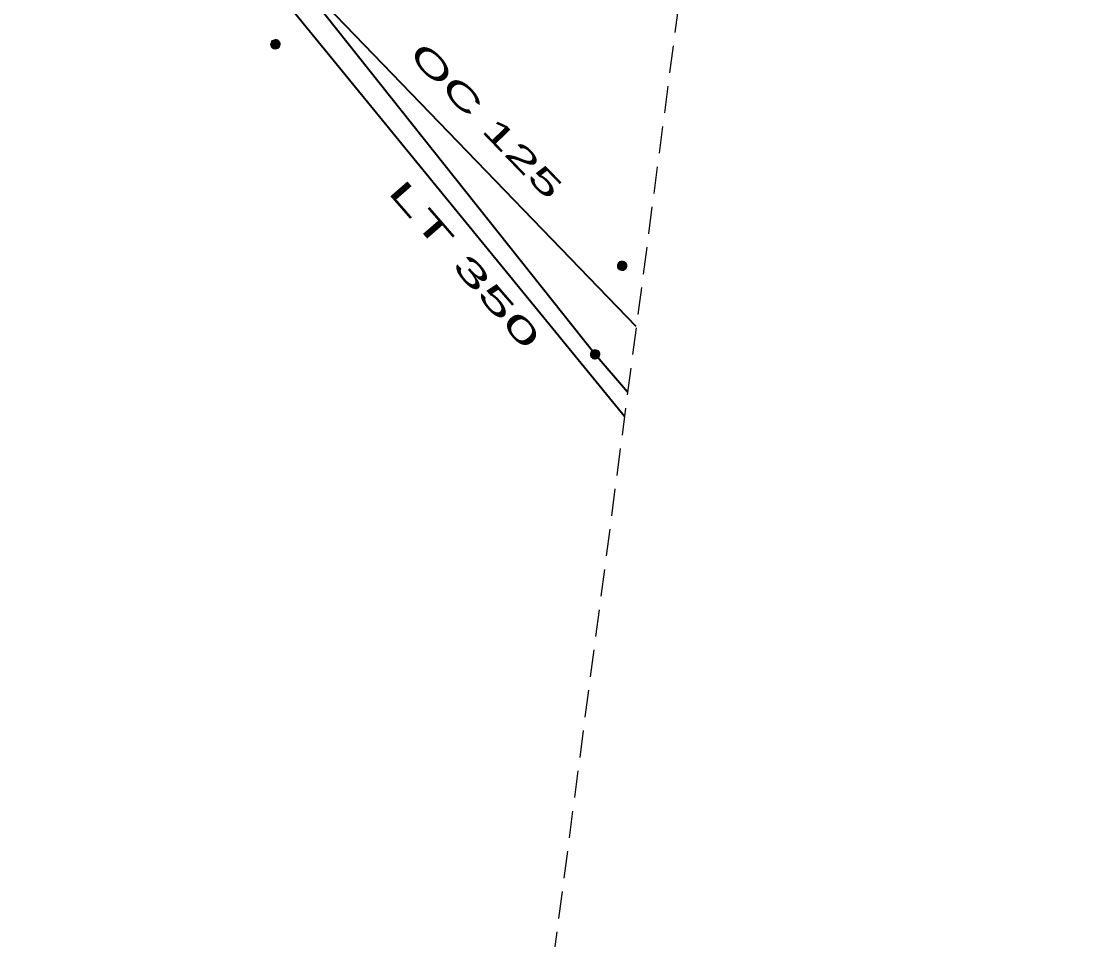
# Model space of a CAD drawing. Extents: x -867121 to -866743, y -1014362 to -1014088.
# Drawn here: x -866794.7 to -866742.8, y -1014314.8 to -1014270 of the extents above; entities that cross this region are included whole.
import ezdxf

# ---------------------------------------------------------------- set-up
doc = ezdxf.new("R2010")
doc.units = 0
doc.header["$LTSCALE"] = 0.44
doc.linetypes.add('MEDIUM_DASHED', pattern=[4.5, 3, -1.5])
for name, color, linetype, lineweight in [('1', 7, 'Continuous', 35), ('21', 7, 'Continuous', 35), ('25', 7, 'Continuous', 13), ('32', 7, 'Continuous', 13), ('62', 7, 'MEDIUM_DASHED', 25)]:
    doc.layers.add(name, color=color, linetype=linetype, lineweight=lineweight)

msp = doc.modelspace()

# ---------------------------------------------------------------- linework, layer by layer
at = {"layer": '1'}
for p, q in [((-866764.699, -1014284.885), (-866792.574, -1014256.008)), ((-866765.275, -1014289.274), (-866791.98, -1014256.58))]:
    msp.add_line(p, q, dxfattribs=at)
at = {"layer": '21'}
msp.add_lwpolyline([(-866765.121, -1014288.097), (-866766.707, -1014286.245), (-866790.339, -1014256.505)], dxfattribs=at)
at = {"layer": '25'}
for points in [[(-866782.059, -1014271.13), (-866782.065, -1014271.078), (-866782.082, -1014271.028), (-866782.111, -1014270.984), (-866782.148, -1014270.947), (-866782.193, -1014270.92), (-866782.243, -1014270.903), (-866782.296, -1014270.899), (-866782.348, -1014270.906), (-866782.397, -1014270.925), (-866782.44, -1014270.954), (-866782.476, -1014270.993), (-866782.502, -1014271.038), (-866782.518, -1014271.089), (-866782.521, -1014271.141), (-866782.513, -1014271.193), (-866782.493, -1014271.242), (-866782.462, -1014271.285), (-866782.423, -1014271.319), (-866782.377, -1014271.345), (-866782.326, -1014271.359), (-866782.273, -1014271.361), (-866782.222, -1014271.351), (-866782.174, -1014271.33), (-866782.131, -1014271.299), (-866782.097, -1014271.258), (-866782.073, -1014271.212), (-866782.061, -1014271.161)], [(-866782.089, -1014271.13), (-866782.095, -1014271.081), (-866782.112, -1014271.035), (-866782.14, -1014270.995), (-866782.177, -1014270.963), (-866782.221, -1014270.941), (-866782.269, -1014270.93), (-866782.318, -1014270.93), (-866782.365, -1014270.943), (-866782.408, -1014270.967), (-866782.444, -1014271), (-866782.471, -1014271.041), (-866782.487, -1014271.088), (-866782.491, -1014271.137), (-866782.484, -1014271.185), (-866782.465, -1014271.23), (-866782.435, -1014271.27), (-866782.397, -1014271.301), (-866782.353, -1014271.321), (-866782.305, -1014271.331), (-866782.256, -1014271.329), (-866782.209, -1014271.314), (-866782.166, -1014271.289), (-866782.132, -1014271.255), (-866782.106, -1014271.213), (-866782.092, -1014271.166)], [(-866782.119, -1014271.13), (-866782.125, -1014271.085), (-866782.142, -1014271.043), (-866782.17, -1014271.008), (-866782.206, -1014270.981), (-866782.248, -1014270.964), (-866782.293, -1014270.959), (-866782.338, -1014270.965), (-866782.379, -1014270.984), (-866782.414, -1014271.012), (-866782.441, -1014271.049), (-866782.457, -1014271.091), (-866782.461, -1014271.136), (-866782.454, -1014271.181), (-866782.435, -1014271.222), (-866782.406, -1014271.256), (-866782.369, -1014271.282), (-866782.326, -1014271.298), (-866782.281, -1014271.301), (-866782.236, -1014271.293), (-866782.196, -1014271.273), (-866782.162, -1014271.244), (-866782.136, -1014271.206), (-866782.122, -1014271.163)], [(-866782.149, -1014271.13), (-866782.154, -1014271.089), (-866782.172, -1014271.052), (-866782.199, -1014271.021), (-866782.234, -1014271), (-866782.274, -1014270.989), (-866782.315, -1014270.991), (-866782.354, -1014271.004), (-866782.388, -1014271.028), (-866782.413, -1014271.06), (-866782.428, -1014271.098), (-866782.431, -1014271.139), (-866782.423, -1014271.179), (-866782.403, -1014271.215), (-866782.374, -1014271.244), (-866782.337, -1014271.263), (-866782.297, -1014271.271), (-866782.256, -1014271.267), (-866782.218, -1014271.252), (-866782.186, -1014271.226), (-866782.163, -1014271.192), (-866782.15, -1014271.153)], [(-866782.179, -1014271.13), (-866782.184, -1014271.094), (-866782.202, -1014271.062), (-866782.228, -1014271.037), (-866782.262, -1014271.022), (-866782.298, -1014271.019), (-866782.333, -1014271.027), (-866782.364, -1014271.047), (-866782.387, -1014271.075), (-866782.4, -1014271.109), (-866782.4, -1014271.146), (-866782.389, -1014271.181), (-866782.368, -1014271.21), (-866782.338, -1014271.231), (-866782.303, -1014271.241), (-866782.266, -1014271.239), (-866782.232, -1014271.225), (-866782.205, -1014271.202), (-866782.186, -1014271.17), (-866782.179, -1014271.135)], [(-866782.209, -1014271.13), (-866782.214, -1014271.099), (-866782.231, -1014271.073), (-866782.257, -1014271.056), (-866782.287, -1014271.049), (-866782.318, -1014271.053), (-866782.345, -1014271.07), (-866782.363, -1014271.094), (-866782.371, -1014271.125), (-866782.367, -1014271.155), (-866782.352, -1014271.183), (-866782.328, -1014271.202), (-866782.298, -1014271.211), (-866782.267, -1014271.208), (-866782.239, -1014271.194), (-866782.219, -1014271.17), (-866782.209, -1014271.141)], [(-866782.239, -1014271.13), (-866782.244, -1014271.106), (-866782.261, -1014271.088), (-866782.284, -1014271.079), (-866782.308, -1014271.082), (-866782.329, -1014271.096), (-866782.34, -1014271.118), (-866782.34, -1014271.143), (-866782.328, -1014271.164), (-866782.308, -1014271.178), (-866782.283, -1014271.181), (-866782.26, -1014271.172), (-866782.244, -1014271.154)], [(-866782.269, -1014271.13), (-866782.274, -1014271.115), (-866782.289, -1014271.109), (-866782.304, -1014271.113), (-866782.311, -1014271.127), (-866782.307, -1014271.142), (-866782.294, -1014271.151), (-866782.279, -1014271.148), (-866782.269, -1014271.136)], [(-866765.159, -1014281.93), (-866765.165, -1014281.878), (-866765.182, -1014281.828), (-866765.211, -1014281.784), (-866765.248, -1014281.747), (-866765.293, -1014281.72), (-866765.343, -1014281.703), (-866765.396, -1014281.699), (-866765.448, -1014281.706), (-866765.497, -1014281.725), (-866765.54, -1014281.754), (-866765.576, -1014281.793), (-866765.602, -1014281.838), (-866765.618, -1014281.889), (-866765.621, -1014281.941), (-866765.613, -1014281.993), (-866765.593, -1014282.042), (-866765.562, -1014282.085), (-866765.523, -1014282.119), (-866765.477, -1014282.145), (-866765.426, -1014282.159), (-866765.373, -1014282.161), (-866765.322, -1014282.151), (-866765.274, -1014282.13), (-866765.231, -1014282.099), (-866765.197, -1014282.058), (-866765.173, -1014282.012), (-866765.161, -1014281.961)], [(-866765.189, -1014281.93), (-866765.195, -1014281.881), (-866765.212, -1014281.835), (-866765.24, -1014281.795), (-866765.277, -1014281.763), (-866765.321, -1014281.741), (-866765.369, -1014281.73), (-866765.418, -1014281.73), (-866765.465, -1014281.743), (-866765.508, -1014281.767), (-866765.544, -1014281.8), (-866765.571, -1014281.841), (-866765.587, -1014281.888), (-866765.591, -1014281.937), (-866765.584, -1014281.985), (-866765.565, -1014282.03), (-866765.535, -1014282.07), (-866765.497, -1014282.101), (-866765.453, -1014282.121), (-866765.405, -1014282.131), (-866765.356, -1014282.129), (-866765.309, -1014282.114), (-866765.266, -1014282.089), (-866765.232, -1014282.055), (-866765.206, -1014282.013), (-866765.192, -1014281.966)], [(-866765.219, -1014281.93), (-866765.225, -1014281.885), (-866765.242, -1014281.843), (-866765.27, -1014281.808), (-866765.306, -1014281.781), (-866765.348, -1014281.764), (-866765.393, -1014281.759), (-866765.438, -1014281.765), (-866765.479, -1014281.784), (-866765.514, -1014281.812), (-866765.541, -1014281.849), (-866765.557, -1014281.891), (-866765.561, -1014281.936), (-866765.554, -1014281.981), (-866765.535, -1014282.022), (-866765.506, -1014282.056), (-866765.469, -1014282.082), (-866765.426, -1014282.098), (-866765.381, -1014282.101), (-866765.336, -1014282.093), (-866765.296, -1014282.073), (-866765.262, -1014282.044), (-866765.236, -1014282.006), (-866765.222, -1014281.963)], [(-866765.249, -1014281.93), (-866765.254, -1014281.889), (-866765.272, -1014281.852), (-866765.299, -1014281.821), (-866765.334, -1014281.8), (-866765.374, -1014281.789), (-866765.415, -1014281.791), (-866765.454, -1014281.804), (-866765.488, -1014281.828), (-866765.513, -1014281.86), (-866765.528, -1014281.898), (-866765.531, -1014281.939), (-866765.523, -1014281.979), (-866765.503, -1014282.015), (-866765.474, -1014282.044), (-866765.437, -1014282.063), (-866765.397, -1014282.071), (-866765.356, -1014282.067), (-866765.318, -1014282.052), (-866765.286, -1014282.026), (-866765.263, -1014281.992), (-866765.25, -1014281.953)], [(-866765.279, -1014281.93), (-866765.284, -1014281.894), (-866765.302, -1014281.862), (-866765.328, -1014281.837), (-866765.362, -1014281.822), (-866765.398, -1014281.819), (-866765.433, -1014281.827), (-866765.464, -1014281.847), (-866765.487, -1014281.875), (-866765.5, -1014281.909), (-866765.5, -1014281.946), (-866765.489, -1014281.981), (-866765.468, -1014282.01), (-866765.438, -1014282.031), (-866765.403, -1014282.041), (-866765.366, -1014282.039), (-866765.332, -1014282.025), (-866765.305, -1014282.002), (-866765.286, -1014281.97), (-866765.279, -1014281.935)], [(-866765.309, -1014281.93), (-866765.314, -1014281.899), (-866765.331, -1014281.873), (-866765.357, -1014281.856), (-866765.387, -1014281.849), (-866765.418, -1014281.853), (-866765.445, -1014281.87), (-866765.463, -1014281.894), (-866765.471, -1014281.925), (-866765.467, -1014281.955), (-866765.452, -1014281.983), (-866765.428, -1014282.002), (-866765.398, -1014282.011), (-866765.367, -1014282.008), (-866765.339, -1014281.994), (-866765.319, -1014281.97), (-866765.309, -1014281.941)], [(-866765.339, -1014281.93), (-866765.344, -1014281.906), (-866765.361, -1014281.888), (-866765.384, -1014281.879), (-866765.408, -1014281.882), (-866765.429, -1014281.896), (-866765.44, -1014281.918), (-866765.44, -1014281.943), (-866765.428, -1014281.964), (-866765.408, -1014281.978), (-866765.383, -1014281.981), (-866765.36, -1014281.972), (-866765.344, -1014281.954)], [(-866765.369, -1014281.93), (-866765.374, -1014281.915), (-866765.389, -1014281.909), (-866765.404, -1014281.913), (-866765.411, -1014281.927), (-866765.407, -1014281.942), (-866765.394, -1014281.951), (-866765.379, -1014281.948), (-866765.369, -1014281.936)]]:
    msp.add_lwpolyline(points, close=True, dxfattribs=at)
at = {"layer": '32'}
for points in [[(-866766.476, -1014286.245), (-866766.482, -1014286.193), (-866766.499, -1014286.143), (-866766.528, -1014286.099), (-866766.565, -1014286.062), (-866766.61, -1014286.035), (-866766.66, -1014286.018), (-866766.713, -1014286.014), (-866766.765, -1014286.021), (-866766.814, -1014286.04), (-866766.857, -1014286.069), (-866766.893, -1014286.108), (-866766.919, -1014286.153), (-866766.935, -1014286.204), (-866766.938, -1014286.256), (-866766.93, -1014286.308), (-866766.91, -1014286.357), (-866766.879, -1014286.4), (-866766.84, -1014286.434), (-866766.794, -1014286.46), (-866766.743, -1014286.474), (-866766.69, -1014286.476), (-866766.639, -1014286.466), (-866766.591, -1014286.445), (-866766.548, -1014286.414), (-866766.514, -1014286.373), (-866766.49, -1014286.327), (-866766.478, -1014286.276)], [(-866766.506, -1014286.245), (-866766.512, -1014286.196), (-866766.529, -1014286.15), (-866766.557, -1014286.11), (-866766.594, -1014286.078), (-866766.638, -1014286.056), (-866766.686, -1014286.045), (-866766.735, -1014286.045), (-866766.782, -1014286.058), (-866766.825, -1014286.082), (-866766.861, -1014286.115), (-866766.888, -1014286.156), (-866766.904, -1014286.203), (-866766.908, -1014286.252), (-866766.901, -1014286.3), (-866766.882, -1014286.345), (-866766.852, -1014286.385), (-866766.814, -1014286.416), (-866766.77, -1014286.436), (-866766.722, -1014286.446), (-866766.673, -1014286.444), (-866766.626, -1014286.429), (-866766.583, -1014286.404), (-866766.549, -1014286.37), (-866766.523, -1014286.328), (-866766.509, -1014286.281)], [(-866766.536, -1014286.245), (-866766.542, -1014286.2), (-866766.559, -1014286.158), (-866766.587, -1014286.123), (-866766.623, -1014286.096), (-866766.665, -1014286.079), (-866766.71, -1014286.074), (-866766.755, -1014286.08), (-866766.796, -1014286.099), (-866766.831, -1014286.127), (-866766.858, -1014286.164), (-866766.874, -1014286.206), (-866766.878, -1014286.251), (-866766.871, -1014286.296), (-866766.852, -1014286.337), (-866766.823, -1014286.371), (-866766.786, -1014286.397), (-866766.743, -1014286.413), (-866766.698, -1014286.416), (-866766.653, -1014286.408), (-866766.613, -1014286.388), (-866766.579, -1014286.359), (-866766.553, -1014286.321), (-866766.539, -1014286.278)], [(-866766.566, -1014286.245), (-866766.571, -1014286.204), (-866766.589, -1014286.167), (-866766.616, -1014286.136), (-866766.651, -1014286.115), (-866766.691, -1014286.104), (-866766.732, -1014286.106), (-866766.771, -1014286.119), (-866766.805, -1014286.143), (-866766.83, -1014286.175), (-866766.845, -1014286.213), (-866766.848, -1014286.254), (-866766.84, -1014286.294), (-866766.82, -1014286.33), (-866766.791, -1014286.359), (-866766.754, -1014286.378), (-866766.714, -1014286.386), (-866766.673, -1014286.382), (-866766.635, -1014286.367), (-866766.603, -1014286.341), (-866766.58, -1014286.307), (-866766.567, -1014286.268)], [(-866766.596, -1014286.245), (-866766.601, -1014286.209), (-866766.619, -1014286.177), (-866766.645, -1014286.152), (-866766.679, -1014286.137), (-866766.715, -1014286.134), (-866766.75, -1014286.142), (-866766.781, -1014286.162), (-866766.804, -1014286.19), (-866766.817, -1014286.224), (-866766.817, -1014286.261), (-866766.806, -1014286.296), (-866766.785, -1014286.325), (-866766.755, -1014286.346), (-866766.72, -1014286.356), (-866766.683, -1014286.354), (-866766.649, -1014286.34), (-866766.622, -1014286.317), (-866766.603, -1014286.285), (-866766.596, -1014286.25)], [(-866766.626, -1014286.245), (-866766.631, -1014286.214), (-866766.648, -1014286.188), (-866766.674, -1014286.171), (-866766.704, -1014286.164), (-866766.735, -1014286.168), (-866766.762, -1014286.185), (-866766.78, -1014286.209), (-866766.788, -1014286.24), (-866766.784, -1014286.27), (-866766.769, -1014286.298), (-866766.745, -1014286.317), (-866766.715, -1014286.326), (-866766.684, -1014286.323), (-866766.656, -1014286.309), (-866766.636, -1014286.285), (-866766.626, -1014286.256)], [(-866766.656, -1014286.245), (-866766.661, -1014286.221), (-866766.678, -1014286.203), (-866766.701, -1014286.194), (-866766.725, -1014286.197), (-866766.746, -1014286.211), (-866766.757, -1014286.233), (-866766.757, -1014286.258), (-866766.745, -1014286.279), (-866766.725, -1014286.293), (-866766.7, -1014286.296), (-866766.677, -1014286.287), (-866766.661, -1014286.269)], [(-866766.686, -1014286.245), (-866766.691, -1014286.23), (-866766.706, -1014286.224), (-866766.721, -1014286.228), (-866766.728, -1014286.242), (-866766.724, -1014286.257), (-866766.711, -1014286.266), (-866766.696, -1014286.263), (-866766.686, -1014286.251)]]:
    msp.add_lwpolyline(points, close=True, dxfattribs=at)
at = {"layer": '62'}
msp.add_lwpolyline([(-867067.961, -1014088.34), (-866742.796, -1014118.083), (-866768.922, -1014317.041), (-866980.741, -1014362.46), (-867121.419, -1014295.739)], close=True, dxfattribs=at)

# ---------------------------------------------------------------- texts
at = {"layer": '1'}
for s, rotation, width, p in [('OC 125', 314, 1.95, (-866775.844, -1014271.682)), ('LT 350', 311, 2.25, (-866776.864, -1014278.335))]:
    msp.add_text(s, height=1.1, rotation=rotation, dxfattribs=dict(at, width=width)).set_placement(p)

doc.saveas('drawing.dxf')
